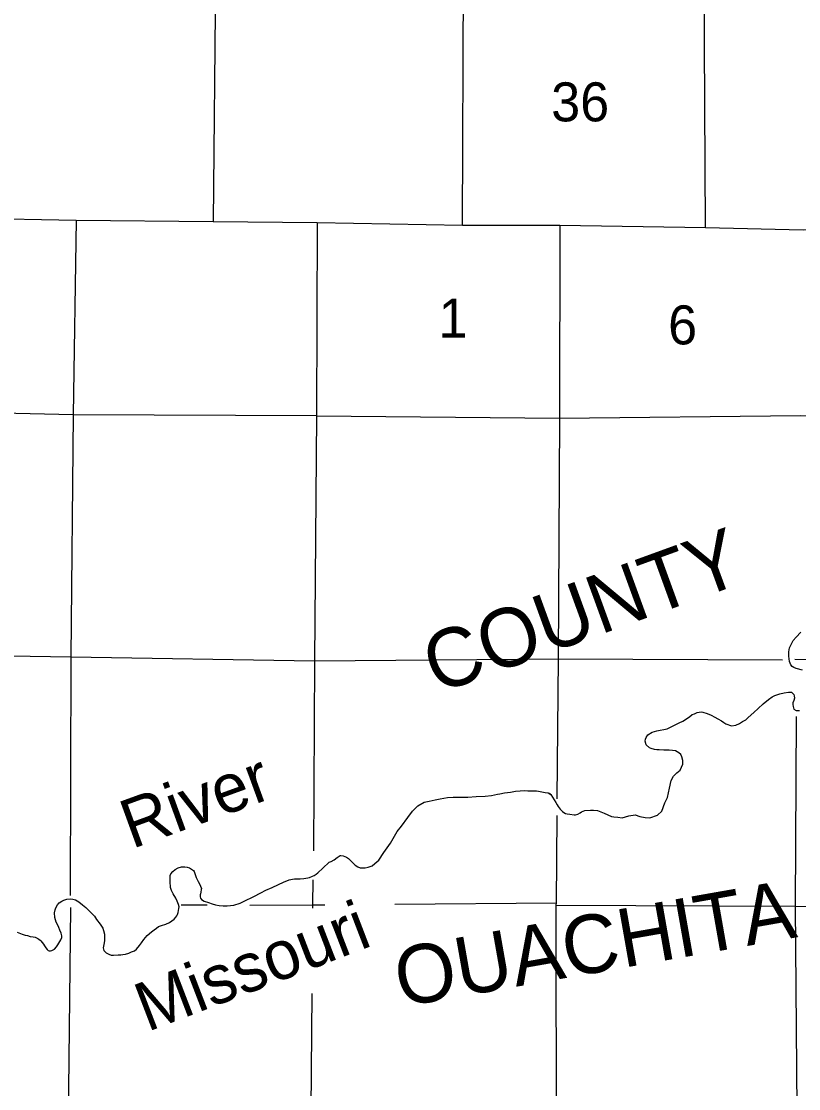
# Model space of a CAD drawing. Extents: x 369523 to 838377, y 495025 to 936819.
# Drawn here: x 596328 to 613164, y 646707 to 669834 of the extents above; entities that cross this region are included whole.
import ezdxf

# ---------------------------------------------------------------- set-up
doc = ezdxf.new("R2010")
doc.units = 0
for name, color, linetype in [('21', 7, 'Continuous'), ('Level 10', 7, 'Continuous'), ('Level 15', 7, 'Continuous'), ('Level 22', 7, 'Continuous'), ('Level 6', 7, 'Continuous')]:
    doc.layers.add(name, color=color, linetype=linetype)

msp = doc.modelspace()

# ---------------------------------------------------------------- linework, layer by layer
at = {"layer": 'Level 15'}
for points in [[(611148, 665368), (611118, 670706), (611131, 676019), (611208, 681262), (611205, 681330), (611162, 686606), (611157, 686666)], [(568578, 665834), (570960, 665869), (573906, 665838), (576238, 665814), (579238, 665771), (581549, 665711), (584503, 665720), (586903, 665676), (589897, 665633), (592253, 665601), (595264, 665568), (597516, 665528), (600480, 665495), (602734, 665473), (605886, 665418)], [(605886, 665418), (607991, 665418), (611148, 665368), (613262, 665320), (616612, 665336), (618481, 665296), (621877, 665231), (623770, 665192), (625765, 665158)], [(607991, 665418), (607982, 661235), (607957, 656018), (607924, 652986)], [(607820, 640146), (607921, 645387), (607915, 650684), (607916, 650732), (607933, 652622)]]:
    msp.add_lwpolyline(points, dxfattribs=at)
at = {"layer": 'Level 22'}
for points in [[(600612, 686778), (600576, 681512), (600536, 676091), (600534, 670794), (600480, 665495)], [(605886, 665418), (605906, 670727), (605946, 676006), (605992, 681400), (605958, 686705)], [(597516, 665528), (597448, 661310), (597398, 656061), (597383, 650893)], [(602734, 665473), (602718, 661287), (602678, 655976), (602657, 651862)], [(602718, 661287), (597448, 661310), (592170, 661427), (586789, 661440), (581491, 661577), (576283, 661672)], [(602718, 661287), (607982, 661235), (613207, 661290), (618538, 661278), (623799, 661189), (624103, 661186)], [(586957, 656207), (592107, 656148), (597398, 656061), (602678, 655976)], [(602678, 655976), (607957, 656018), (612813, 655999)], [(613081, 656010), (618578, 655993), (623784, 655875), (629065, 655755), (634462, 655732), (639666, 655759), (643998, 655781)], [(613120, 640050), (613138, 645364), (613094, 650662), (613116, 654769)], [(602643, 651235), (602634, 650689), (602633, 650614)], [(597390, 650635), (597334, 645386)], [(600353, 650680), (599793, 650686)], [(601274, 650684), (602634, 650689)], [(602634, 650689), (602902, 650691)], [(604420, 650703), (607916, 650732)], [(607915, 650684), (613094, 650662), (618427, 650623), (623738, 650500), (629049, 650405), (634411, 650303), (639697, 650207)], [(602619, 648765), (602593, 645404)]]:
    msp.add_lwpolyline(points, dxfattribs=at)
at = {"layer": 'Level 6'}
for points in [[(613247, 655776), (613113, 655812), (613057, 655831), (613027, 655856), (612996, 655892), (612965, 655964), (612950, 656076), (612952, 656170), (612965, 656260), (613049, 656417), (613108, 656488), (613214, 656600)], [(613247, 655776), (613113, 655812), (613057, 655831), (613027, 655856), (612996, 655892), (612965, 655964), (612950, 656076), (612952, 656170), (612965, 656260), (613049, 656417), (613108, 656488), (613214, 656600)], [(607736, 653115), (607797, 653078), (607832, 653023), (607866, 652967), (607905, 652908), (607936, 652856), (607954, 652818), (607997, 652763), (608046, 652712), (608076, 652688), (608114, 652667), (608152, 652659), (608208, 652654), (608304, 652639), (608328, 652642), (608382, 652657), (608431, 652685), (608463, 652704), (608535, 652733), (608654, 652743), (608718, 652740), (608804, 652731), (608953, 652673), (609029, 652640), (609109, 652605), (609159, 652596), (609245, 652587), (609345, 652573), (609487, 652619), (609622, 652637), (609726, 652607), (609839, 652580), (609942, 652578), (610107, 652631), (610200, 652718), (610269, 652897), (610320, 653014), (610369, 653219), (610400, 653384), (610455, 653475), (610526, 653552), (610595, 653609), (610657, 653740), (610652, 653816), (610632, 653900), (610610, 653946), (610571, 653987), (610495, 654028), (610431, 654037), (610361, 654038), (610243, 654042), (610145, 654045), (610091, 654048), (610045, 654057), (609969, 654076), (609935, 654090), (609862, 654157), (609837, 654238), (609844, 654281), (609858, 654317), (609897, 654370), (609994, 654431), (610091, 654463), (610316, 654506), (610574, 654632), (610653, 654673), (610802, 654764), (610861, 654811), (610905, 654831), (610968, 654854), (611050, 654869), (611092, 654864), (611184, 654837), (611269, 654801), (611349, 654754), (611412, 654717), (611490, 654676), (611546, 654639), (611587, 654609), (611713, 654569), (611801, 654580), (611882, 654620), (611951, 654659), (612017, 654702), (612072, 654747), (612190, 654859), (612285, 654944), (612397, 655046), (612510, 655140), (612589, 655197), (612650, 655226), (612756, 655264), (612853, 655287), (612941, 655298), (612989, 655301), (613007, 655297), (613037, 655272), (613057, 655246), (613066, 655218), (613072, 655170), (613059, 655118)], [(607736, 653115), (607797, 653078), (607832, 653023), (607866, 652967), (607905, 652908), (607936, 652856), (607954, 652818), (607997, 652763), (608046, 652712), (608076, 652688), (608114, 652667), (608152, 652659), (608208, 652654), (608304, 652639), (608328, 652642), (608382, 652657), (608431, 652685), (608463, 652704), (608535, 652733), (608654, 652743), (608718, 652740), (608804, 652731), (608953, 652673), (609029, 652640), (609109, 652605), (609159, 652596), (609245, 652587), (609345, 652573), (609487, 652619), (609622, 652637), (609726, 652607), (609839, 652580), (609942, 652578), (610107, 652631), (610200, 652718), (610269, 652897), (610320, 653014), (610369, 653219), (610400, 653384), (610455, 653475), (610526, 653552), (610595, 653609), (610657, 653740), (610652, 653816), (610632, 653900), (610610, 653946), (610571, 653987), (610495, 654028), (610431, 654037), (610361, 654038), (610243, 654042), (610145, 654045), (610091, 654048), (610045, 654057), (609969, 654076), (609935, 654090), (609862, 654157), (609837, 654238), (609844, 654281), (609858, 654317), (609897, 654370), (609994, 654431), (610091, 654463), (610316, 654506), (610574, 654632), (610653, 654673), (610802, 654764), (610861, 654811), (610905, 654831), (610968, 654854), (611050, 654869), (611092, 654864), (611184, 654837), (611269, 654801), (611349, 654754), (611412, 654717), (611490, 654676), (611546, 654639), (611587, 654609), (611713, 654569), (611801, 654580), (611882, 654620), (611951, 654659), (612017, 654702), (612072, 654747), (612190, 654859), (612285, 654944), (612397, 655046), (612510, 655140), (612589, 655197), (612650, 655226), (612756, 655264), (612853, 655287), (612941, 655298), (612989, 655301), (613007, 655297), (613037, 655272), (613057, 655246), (613066, 655218), (613072, 655170), (613059, 655118)], [(613059, 655118), (613040, 655064), (613038, 655028), (613043, 654986), (613060, 654932), (613112, 654901), (613184, 654898)], [(613059, 655118), (613040, 655064), (613038, 655028), (613043, 654986), (613060, 654932), (613112, 654901), (613184, 654898)], [(603617, 651510), (603665, 651491), (603715, 651489), (603774, 651489), (603842, 651503), (603926, 651535), (603986, 651583), (604072, 651661), (604178, 651827), (604324, 652025), (604470, 652279), (604562, 652393), (604698, 652580), (604798, 652716), (604917, 652838), (605051, 652917), (605159, 652937), (605293, 652963), (605402, 652987), (605556, 653013), (605680, 653025), (605835, 653025), (605997, 653025), (606176, 653035), (606374, 653046), (606509, 653056), (606641, 653086), (606693, 653096), (606793, 653116), (606920, 653134), (607032, 653154), (607132, 653162), (607226, 653164), (607300, 653162), (607395, 653158), (607485, 653159), (607531, 653155), (607603, 653137), (607676, 653121), (607736, 653115), (607784, 653105)], [(603617, 651510), (603665, 651491), (603715, 651489), (603774, 651489), (603842, 651503), (603926, 651535), (603986, 651583), (604072, 651661), (604178, 651827), (604324, 652025), (604470, 652279), (604562, 652393), (604698, 652580), (604798, 652716), (604917, 652838), (605051, 652917), (605159, 652937), (605293, 652963), (605402, 652987), (605556, 653013), (605680, 653025), (605835, 653025), (605997, 653025), (606176, 653035), (606374, 653046), (606509, 653056), (606641, 653086), (606693, 653096), (606793, 653116), (606920, 653134), (607032, 653154), (607132, 653162), (607226, 653164), (607300, 653162), (607395, 653158), (607485, 653159), (607531, 653155), (607603, 653137), (607676, 653121), (607736, 653115), (607784, 653105)], [(598583, 649620), (598653, 649640), (598717, 649668), (598779, 649692), (598825, 649728), (598887, 649806), (598933, 649868), (598981, 649938), (599055, 650028), (599147, 650102), (599207, 650150), (599257, 650184), (599300, 650218), (599360, 650240), (599454, 650274), (599538, 650310), (599588, 650344), (599640, 650382), (599674, 650420), (599694, 650450), (599708, 650482), (599724, 650524), (599734, 650566), (599742, 650610), (599744, 650646), (599734, 650700), (599704, 650770), (599672, 650835), (599617, 650929), (599583, 650999), (599559, 651067), (599553, 651195), (599549, 651281), (599553, 651323), (599569, 651365), (599611, 651413), (599661, 651457), (599727, 651493), (599797, 651515), (599871, 651515), (599921, 651509), (599969, 651495), (600016, 651463), (600056, 651435), (600072, 651409), (600096, 651345), (600118, 651279), (600138, 651237), (600160, 651194), (600186, 651142), (600209, 651092), (600227, 651042), (600225, 651020), (600217, 650966), (600205, 650930), (600201, 650910), (600201, 650882), (600203, 650862), (600211, 650832), (600227, 650806), (600285, 650772), (600378, 650740), (600460, 650710), (600530, 650692), (600610, 650676), (600697, 650665), (600789, 650665), (600929, 650683), (601067, 650723), (601154, 650767), (601366, 650867), (601514, 650953), (601621, 651005), (601757, 651065), (601897, 651129), (602005, 651181), (602128, 651229), (602202, 651249), (602242, 651251), (602366, 651254), (602450, 651258), (602535, 651272), (602567, 651284), (602633, 651308), (602667, 651324), (602715, 651352), (602749, 651382), (602855, 651484), (602997, 651612), (603039, 651628), (603102, 651668), (603166, 651712), (603236, 651760), (603248, 651762), (603300, 651754), (603374, 651726), (603412, 651696), (603461, 651644), (603513, 651594), (603561, 651550), (603617, 651510)], [(598583, 649620), (598653, 649640), (598717, 649668), (598779, 649692), (598825, 649728), (598887, 649806), (598933, 649868), (598981, 649938), (599055, 650028), (599147, 650102), (599207, 650150), (599257, 650184), (599300, 650218), (599360, 650240), (599454, 650274), (599538, 650310), (599588, 650344), (599640, 650382), (599674, 650420), (599694, 650450), (599708, 650482), (599724, 650524), (599734, 650566), (599742, 650610), (599744, 650646), (599734, 650700), (599704, 650770), (599672, 650835), (599617, 650929), (599583, 650999), (599559, 651067), (599553, 651195), (599549, 651281), (599553, 651323), (599569, 651365), (599611, 651413), (599661, 651457), (599727, 651493), (599797, 651515), (599871, 651515), (599921, 651509), (599969, 651495), (600016, 651463), (600056, 651435), (600072, 651409), (600096, 651345), (600118, 651279), (600138, 651237), (600160, 651194), (600186, 651142), (600209, 651092), (600227, 651042), (600225, 651020), (600217, 650966), (600205, 650930), (600201, 650910), (600201, 650882), (600203, 650862), (600211, 650832), (600227, 650806), (600285, 650772), (600378, 650740), (600460, 650710), (600530, 650692), (600610, 650676), (600697, 650665), (600789, 650665), (600929, 650683), (601067, 650723), (601154, 650767), (601366, 650867), (601514, 650953), (601621, 651005), (601757, 651065), (601897, 651129), (602005, 651181), (602128, 651229), (602202, 651249), (602242, 651251), (602366, 651254), (602450, 651258), (602535, 651272), (602567, 651284), (602633, 651308), (602667, 651324), (602715, 651352), (602749, 651382), (602855, 651484), (602997, 651612), (603039, 651628), (603102, 651668), (603166, 651712), (603236, 651760), (603248, 651762), (603300, 651754), (603374, 651726), (603412, 651696), (603461, 651644), (603513, 651594), (603561, 651550), (603617, 651510)], [(596238, 650097), (596348, 650057), (596414, 650033), (596458, 650023), (596520, 650007), (596583, 649997), (596627, 649987), (596657, 649975), (596685, 649961), (596703, 649949), (596735, 649922), (596749, 649912), (596781, 649872), (596807, 649838), (596830, 649802), (596858, 649760), (596886, 649722), (596912, 649700), (596928, 649694), (596958, 649694), (596990, 649700), (596990, 649702), (597046, 649730), (597090, 649780), (597118, 649820), (597140, 649860), (597158, 649892), (597180, 649928), (597202, 649984), (597204, 650018), (597190, 650076), (597162, 650140), (597138, 650200), (597108, 650264), (597085, 650315), (597053, 650417), (597045, 650513), (597057, 650579), (597075, 650625), (597109, 650687), (597145, 650731), (597207, 650769), (597249, 650789), (597311, 650813), (597388, 650817), (597440, 650811), (597500, 650795), (597572, 650752), (597654, 650692), (597725, 650630), (597813, 650542), (597909, 650444), (597956, 650372), (598032, 650270), (598090, 650181), (598110, 650131), (598127, 650053), (598131, 649969), (598127, 649907), (598111, 649831), (598103, 649761), (598109, 649731), (598117, 649701), (598133, 649677), (598167, 649649), (598222, 649621), (598272, 649601), (598326, 649599), (598426, 649603), (598480, 649605), (598524, 649611), (598583, 649620)], [(596238, 650097), (596348, 650057), (596414, 650033), (596458, 650023), (596520, 650007), (596583, 649997), (596627, 649987), (596657, 649975), (596685, 649961), (596703, 649949), (596735, 649922), (596749, 649912), (596781, 649872), (596807, 649838), (596830, 649802), (596858, 649760), (596886, 649722), (596912, 649700), (596928, 649694), (596958, 649694), (596990, 649700), (596990, 649702), (597046, 649730), (597090, 649780), (597118, 649820), (597140, 649860), (597158, 649892), (597180, 649928), (597202, 649984), (597204, 650018), (597190, 650076), (597162, 650140), (597138, 650200), (597108, 650264), (597085, 650315), (597053, 650417), (597045, 650513), (597057, 650579), (597075, 650625), (597109, 650687), (597145, 650731), (597207, 650769), (597249, 650789), (597311, 650813), (597388, 650817), (597440, 650811), (597500, 650795), (597572, 650752), (597654, 650692), (597725, 650630), (597813, 650542), (597909, 650444), (597956, 650372), (598032, 650270), (598090, 650181), (598110, 650131), (598127, 650053), (598131, 649969), (598127, 649907), (598111, 649831), (598103, 649761), (598109, 649731), (598117, 649701), (598133, 649677), (598167, 649649), (598222, 649621), (598272, 649601), (598326, 649599), (598426, 649603), (598480, 649605), (598524, 649611), (598583, 649620)]]:
    msp.add_lwpolyline(points, dxfattribs=at)

# ---------------------------------------------------------------- texts
at = {"layer": '21'}
for s, rotation, p in [('COUNTY', 20, (605325, 655252)), ('OUACHITA', 10, (604538, 648472))]:
    msp.add_text(s, height=1267.2, rotation=rotation, dxfattribs=at).set_placement(p)
at = {"layer": 'Level 10'}
for s, rotation, p in [('River', 20, (598723, 651896)), ('Missouri', 21, (599055, 647931))]:
    msp.add_text(s, height=1056, rotation=rotation, dxfattribs=at).set_placement(p)
at = {"layer": 'Level 22'}
for s, height, p in [('36', 844.8, (607804, 667667)), ('1', 845, (605363, 662982)), ('6', 845, (610337, 662834))]:
    msp.add_text(s, height=height, dxfattribs=at).set_placement(p)

doc.saveas('drawing.dxf')
